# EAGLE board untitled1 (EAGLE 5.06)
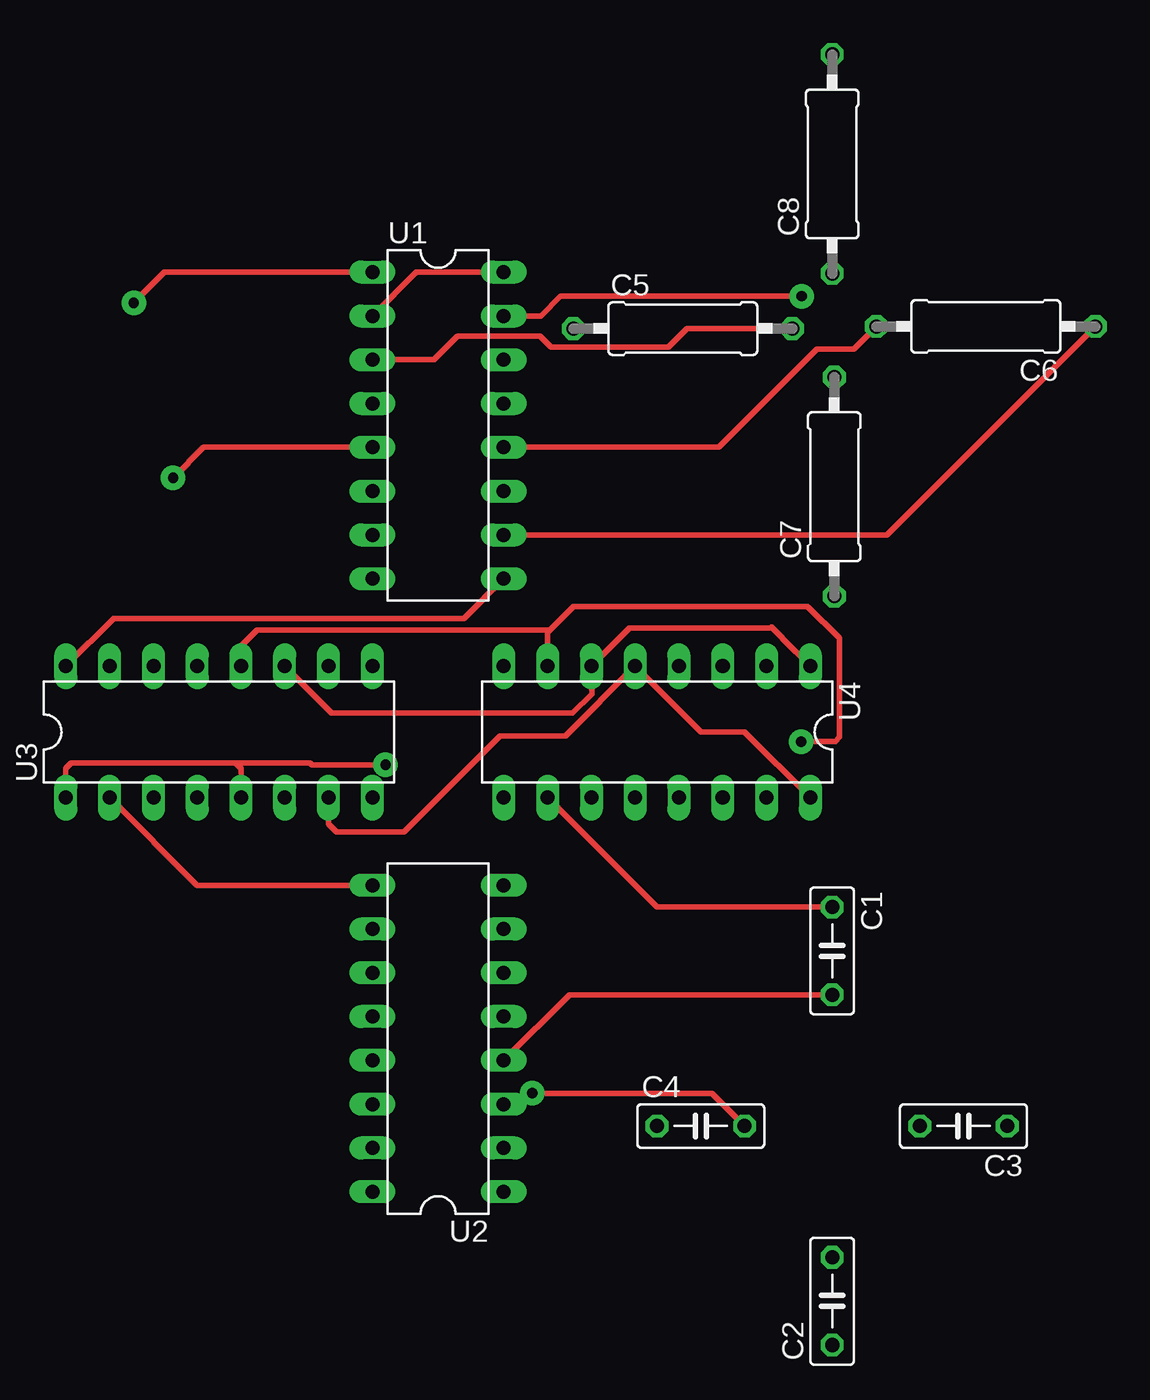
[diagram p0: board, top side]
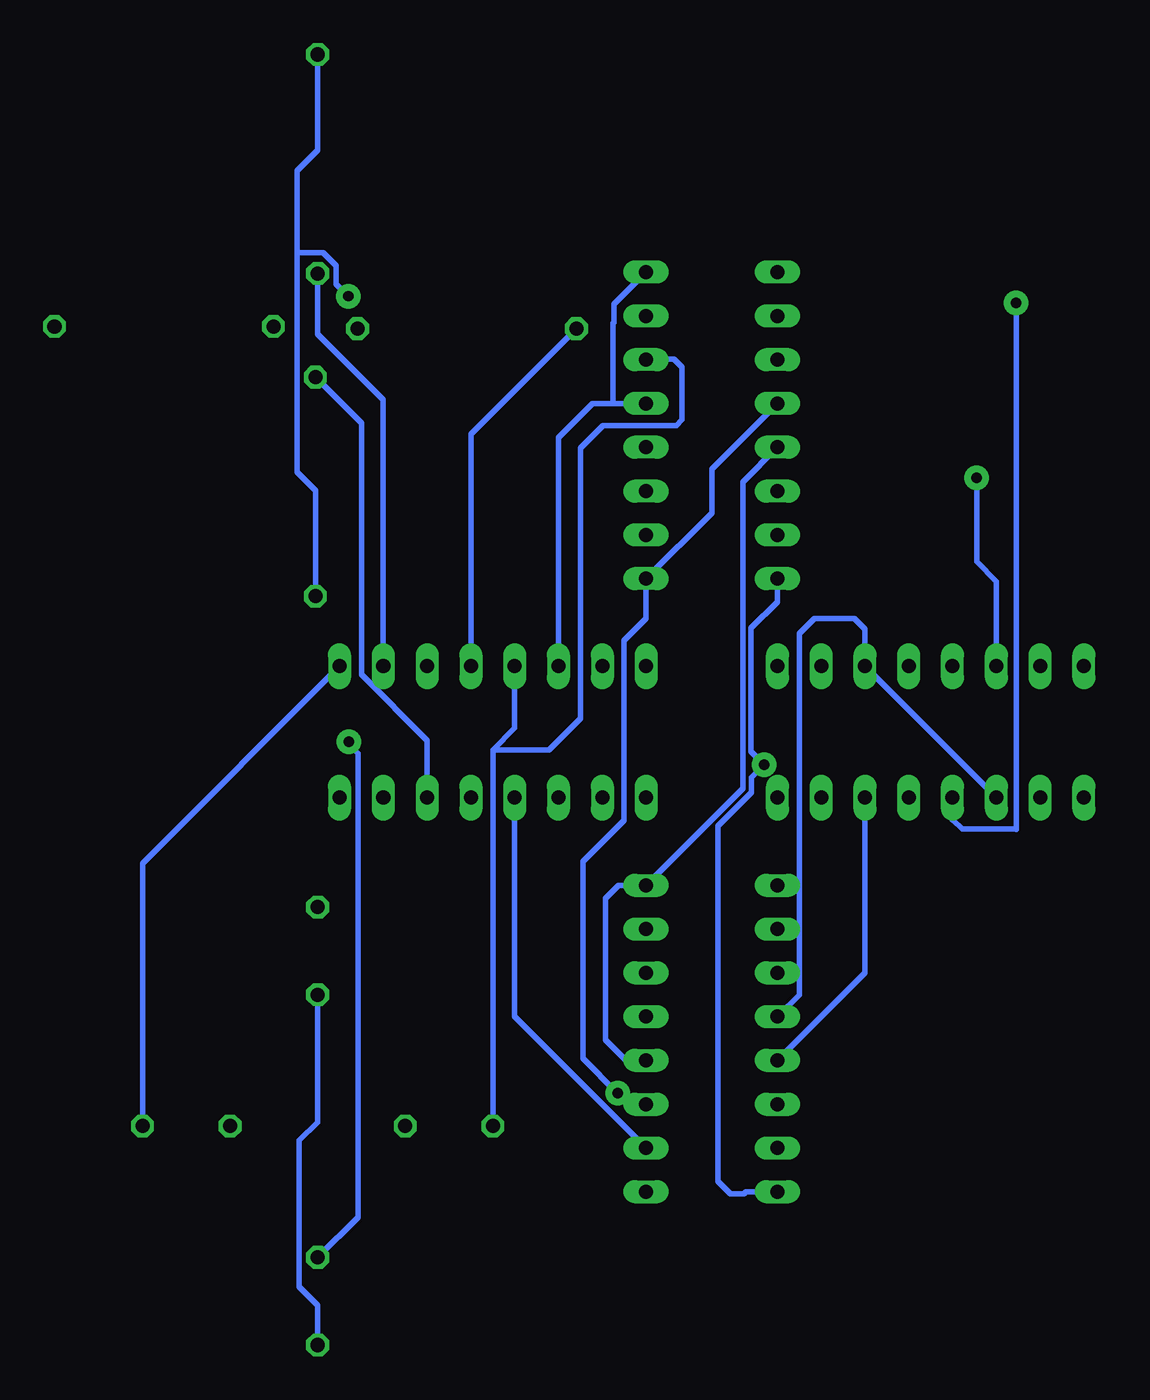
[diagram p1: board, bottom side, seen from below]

No outline drawn. Coordinates in mm, seen from the top.
Copper layers (1*16): Top 0.035mm / dielectric 1.5mm / Bottom 0.035mm
Design rules "default": minimum track width 10mil, minimum drill 24mil, track to track 8mil, track to pad 8mil, pad to pad 8mil, via to via 8mil, smd to smd 8mil, copper to edge 40mil, drill to drill 8mil, minimum pad ring 10mil, minimum via ring 8mil, stop-mask expansion 4mil, vias tented up to drill 0mil, thermal gap 10mil

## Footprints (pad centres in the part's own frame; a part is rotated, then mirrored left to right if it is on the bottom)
C050-025X075 = drill 0.813 octagon: 1 -2.54,0; 2 2.54,0
0309/12 = drill 0.813 octagon: 1 -6.35,0; 2 6.35,0
DIL16 = drill 0.813 long: 1 -8.89,-3.81; 2 -6.35,-3.81; 3 -3.81,-3.81; 4 -1.27,-3.81; 5 1.27,-3.81; 6 3.81,-3.81; 7 6.35,-3.81; 8 8.89,-3.81; 9 8.89,3.81; 10 6.35,3.81; 11 3.81,3.81; 12 1.27,3.81; 13 -1.27,3.81; 14 -3.81,3.81; 15 -6.35,3.81; 16 -8.89,3.81

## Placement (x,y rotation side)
C1  [C050-025X075]  53.34,27.94 270 top
C2  [C050-025X075]  53.34,7.62 90 top
C3  [C050-025X075]  60.96,17.78 180 top
C4  [C050-025X075]  45.72,17.78 0 top
C5  [0309/12]  44.68,64.03 0 top
C6  [0309/12]  62.26,64.16 180 top
C7  [0309/12]  53.47,54.86 90 top
C8  [0309/12]  53.34,73.58 90 top
U1  [DIL16]  30.48,58.42 270 top
U2  [DIL16]  30.48,22.86 90 top
U3  [DIL16]  17.78,40.64 0 top
U4  [DIL16]  43.18,40.64 180 top

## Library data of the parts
C1-C8 U1-U4 = userAA

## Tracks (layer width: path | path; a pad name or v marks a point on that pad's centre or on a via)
#$$$1
  Top 0.305: 8.89,36.83 8.89,38.53 9.2,38.84 18.47,38.84 | 18.47,38.84 18.75,38.84 19.05,38.53 19.05,36.83 | 18.47,38.84 23.06,38.84 23.16,38.73 27.43,38.73
  Bottom 0.305: 26.67,49.53 26.67,48.18 28.19,46.66 28.19,39.5 27.43,38.73 28.17,38 28.17,37.13 30.12,35.18 30.12,14.58 29.39,13.84 28.63,13.84 28.5,13.97 26.67,13.97
#$$$2
  Top 0.305: 8.89,44.45 11.66,47.22 31.98,47.22 34.29,49.53 | 35.94,19.68 46.35,19.68 48.26,17.78
  Bottom 0.305: 26.67,59.69 30.48,55.88 30.48,53.34 34.29,49.53 34.29,47.22 35.56,45.95 35.56,35.51 37.95,33.12 37.95,21.69 35.94,19.68
#$$$3
  Top 0.305: 26.67,64.77 29.21,67.31 34.29,67.31 | 52.07,44.45 50.45,46.07 50.45,46.09 49.81,46.74 49.73,46.66 41.58,46.66 39.37,44.45 39.37,43.13 39.4,43.1 39.4,42.85 38.28,41.73 24.31,41.73 21.59,44.45
  Bottom 0.305: 34.29,59.69 36.2,59.69 | 36.2,59.69 36.2,64.34 36.14,64.39 36.14,65.46 34.29,67.31 | 39.37,44.45 39.37,57.71 37.39,59.69 36.2,59.69 | 13.97,36.83 21.59,44.45 21.59,46.61 22.2,47.22 24.54,47.22 25.4,46.35 25.4,25.4 26.67,24.13 | 63.5,17.78 63.5,33.02 52.07,44.45
#$$$4
  Top 0.305: 34.29,21.59 38.1,25.4 53.34,25.4 | 15.11,55.37 16.89,57.15 26.67,57.15
  Bottom 0.305: 34.29,21.59 35.46,21.59 36.65,22.78 36.65,30.99 35.89,31.75 34.29,31.75 28.68,37.36 28.68,55.14 26.67,57.15 | 13.97,44.45 13.97,49.37 15.11,50.51 15.11,55.37 | 53.34,5.08 53.34,7.39 54.41,8.46 54.41,16.94 53.34,18.01 53.34,25.4
#$$$5
  Top 0.305: 52.07,36.83 48.26,40.64 45.72,40.64 41.91,44.45 37.87,40.41 34.06,40.41 28.5,34.85 24.59,34.85 24.13,35.31 24.13,36.83
  Bottom 0.305: 43.18,17.78 43.18,39.6 | 43.18,39.6 41.91,40.87 41.91,44.45 | 34.29,62.23 33.22,62.23 33.2,62.26 32.66,62.26 32.21,61.8 32.21,58.75 32.54,58.42 36.78,58.42 38.1,57.1 38.1,41.43 39.93,39.6 43.18,39.6
#$$$6
  Top 0.305: 19.05,44.45 19.05,45.62 19.99,46.56 36.98,46.56 | 36.83,44.45 36.83,46.41 36.98,46.56 | 51.54,40.08 53.52,40.08 53.77,40.34 53.77,44.2 53.75,44.22 53.75,46.08 51.92,47.9 38.33,47.9 36.98,46.56
  Bottom 0.305: 53.34,10.16 51,12.5 51,39.38 51.31,39.69 51.31,40.08 51.54,40.08
#$$$7
  Top 0.305: 34.29,64.77 36.45,64.77 37.59,65.91 51.56,65.91
  Bottom 0.305: 51.56,65.91 52.27,66.62 52.27,67.68 53.02,68.43 54.53,68.43 | 54.53,68.43 54.53,73.2 53.34,74.4 53.34,79.93 | 53.47,48.51 53.47,54.63 54.53,55.7 54.53,68.43
#$$$8
  Top 0.305: 34.29,52.07 56.52,52.07 68.61,64.16
#$$$9
  Top 0.305: 36.83,36.83 43.18,30.48 53.34,30.48
#$$$10
  Top 0.305: 12.83,65.53 14.61,67.31 26.67,67.31
  Bottom 0.305: 12.83,65.53 12.83,34.98 12.85,35 15.95,35 16.48,35.53 16.51,35.53 16.51,36.83
#$$$11
  Top 0.305: 11.43,36.83 16.51,31.75 26.67,31.75
#$$$12
  Bottom 0.305: 26.67,21.59 21.59,26.67 21.59,36.83
#$$$13
  Bottom 0.305: 34.29,16.51 41.91,24.13 41.91,36.83
#$$$14
  Top 0.305: 34.29,57.15 46.77,57.15 52.47,62.84 54.59,62.84 55.91,64.16
#$$$15
  Bottom 0.305: 49.53,44.45 49.53,59.91 53.34,63.72 53.34,67.23
#$$$16
  Bottom 0.305: 46.99,36.83 46.99,40.15 50.8,43.96 50.8,58.55 53.47,61.21
#$$$17
  Top 0.305: 26.67,62.23 30.25,62.23 31.62,63.6 36.4,63.6 37.03,62.97 43.84,62.97 44.91,64.03 51.03,64.03
#$$$18
  Bottom 0.305: 44.45,44.45 44.45,57.91 38.33,64.03
S$1  (via drill 0.6 pad 1.42)
  other vias: 35.94,19.68
S$2  (via drill 0.6 pad 1.42)
  other vias: 27.43,38.73
S$3  (via drill 0.6 pad 1.42)
  other vias: 51.54,40.08
S$4  (via drill 0.6 pad 1.42)
  other vias: 15.11,55.37
S$5  (via drill 0.6 pad 1.42)
  other vias: 12.83,65.53
S$6  (via drill 0.6 pad 1.42)
  other vias: 51.56,65.91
